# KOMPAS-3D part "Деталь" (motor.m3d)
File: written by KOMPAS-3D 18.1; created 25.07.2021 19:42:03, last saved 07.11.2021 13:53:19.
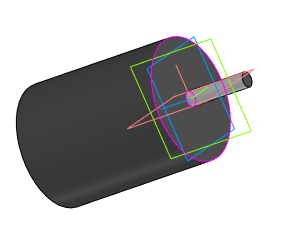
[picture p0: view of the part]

Document properties: Автор: 111; Полное имя файла: C:\Users\admin\Desktop\ffb\motor.m3d

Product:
- Part/product: Деталь
    Масса: 2.13673

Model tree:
1. Эскиз:1
2. Элемент выдавливания:1
     Расстояние 1 = 84
3. Эскиз:2
4. Элемент выдавливания:2
     Расстояние 1 = -35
